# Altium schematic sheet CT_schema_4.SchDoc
size 218 x 258 mm
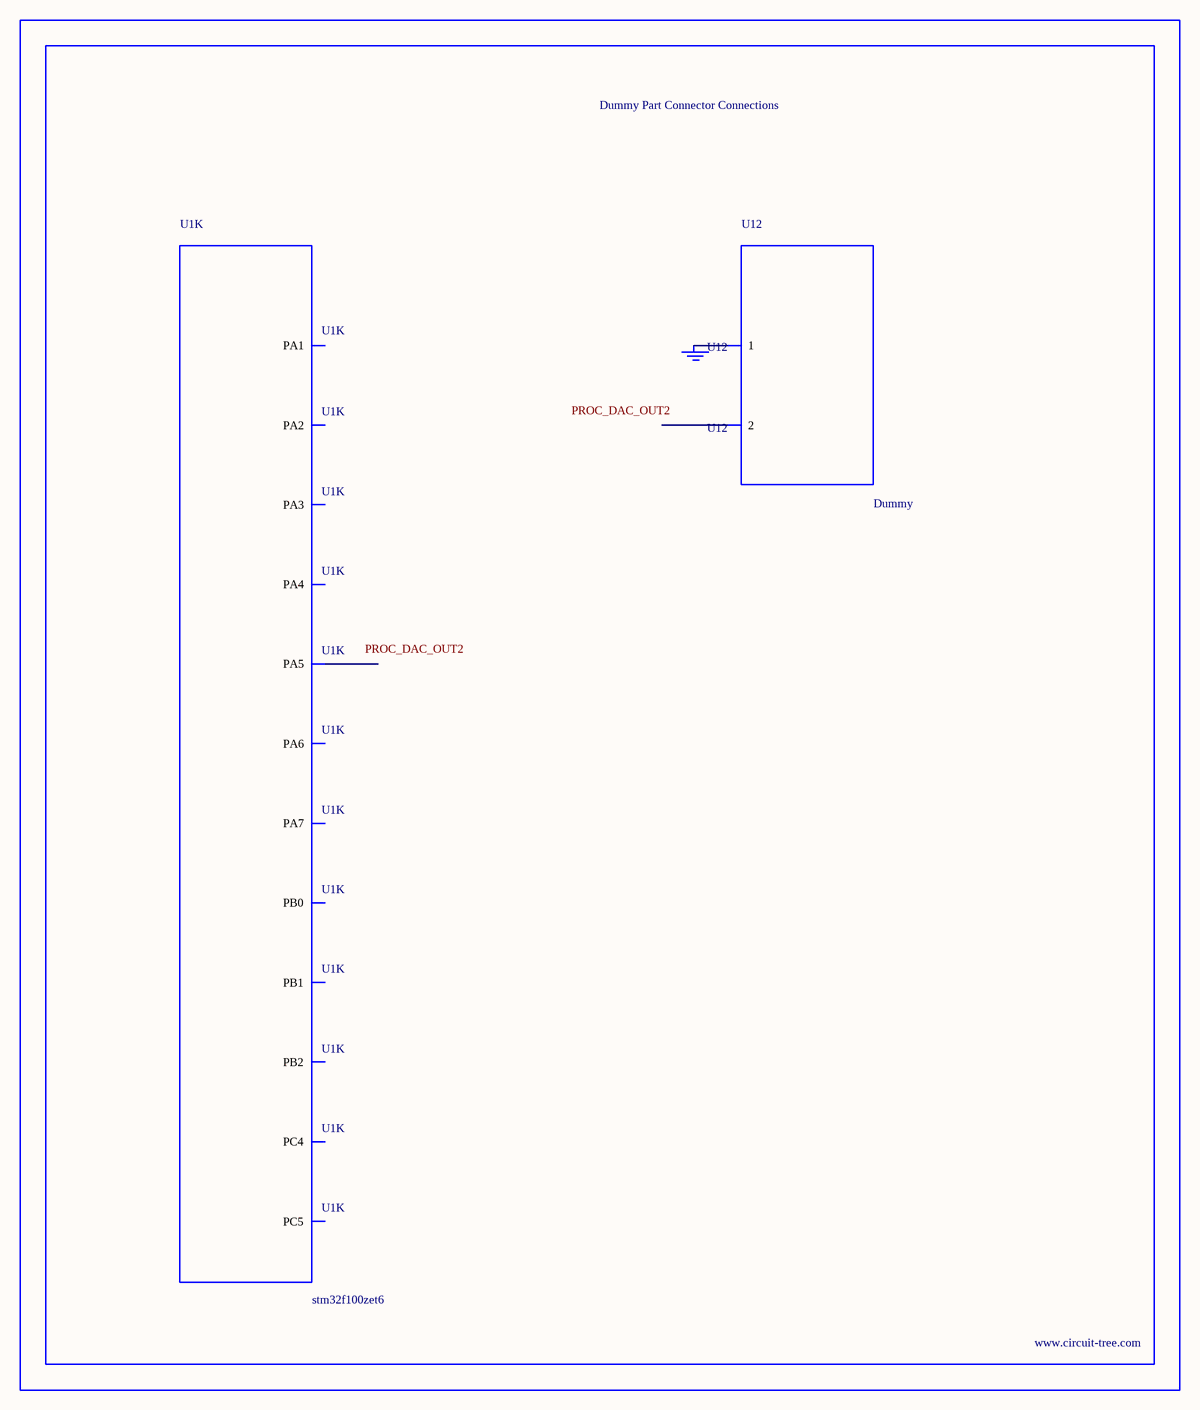
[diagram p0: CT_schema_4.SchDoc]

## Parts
BORDER3  (no value)
GND_INSTANCE_3_0  (no value)
U1  stm32f100zet6  [LQFP144]  (part K of 11)
U12  Dummy  [DUMMY_PACKAGE_140]

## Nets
NetGND_INSTANCE_3_0_0: GND_INSTANCE_3_0.0(GND) U12.1

Not connected (* = marked no-connect by the designer): U1 35(PA1) 36(PA2) 37(PA3) 40(PA4) 41(PA5) 42(PA6) 43(PA7) 44(PC4) 45(PC5) 46(PB0) 47(PB1) 48(PB2); U12 2

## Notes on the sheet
- Labels drawn without touching a wire or pin: PROC_DAC_OUT2

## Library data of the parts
BORDER3 = BORDER_PAGE3
GND_INSTANCE_3_0 = GND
